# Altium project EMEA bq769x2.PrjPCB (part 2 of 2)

## Sheet MCU and Communication.SchDoc
size 431 x 279 mm; Date: Not shown in title block; ApprovedBy: Not shown in title block; CheckedBy: Not shown in title block; Author: Not shown in title block; CompanyName: Not shown in title block; Engineer: Not shown in title block; Organization: Not shown in title block; Address1: Not shown in title block; Address2: Not shown in title block; Address3: Not shown in title block; Address4: Not shown in title block; DocumentNumber: 1; Revision: Use project parameter SCH_Rev; SheetNumber: 4; SheetTotal: 7; PageSetup: Record=PageOptions¦CenterHorizontal=True¦CenterVertical=True¦PrintScale=1.00¦XCorrection=1.00¦YCorrection=1.00¦PrintKind=0¦BorderSize=5000000¦LeftOffset=0¦BottomOffset=0¦Orientation=2¦PaperLength=1000¦PaperWidth=1000¦Scale=100¦PaperSource=15¦PrintQuality=600¦MediaType=1¦DitherType=10¦PaperKind=Letter¦PrintScaleMode=1
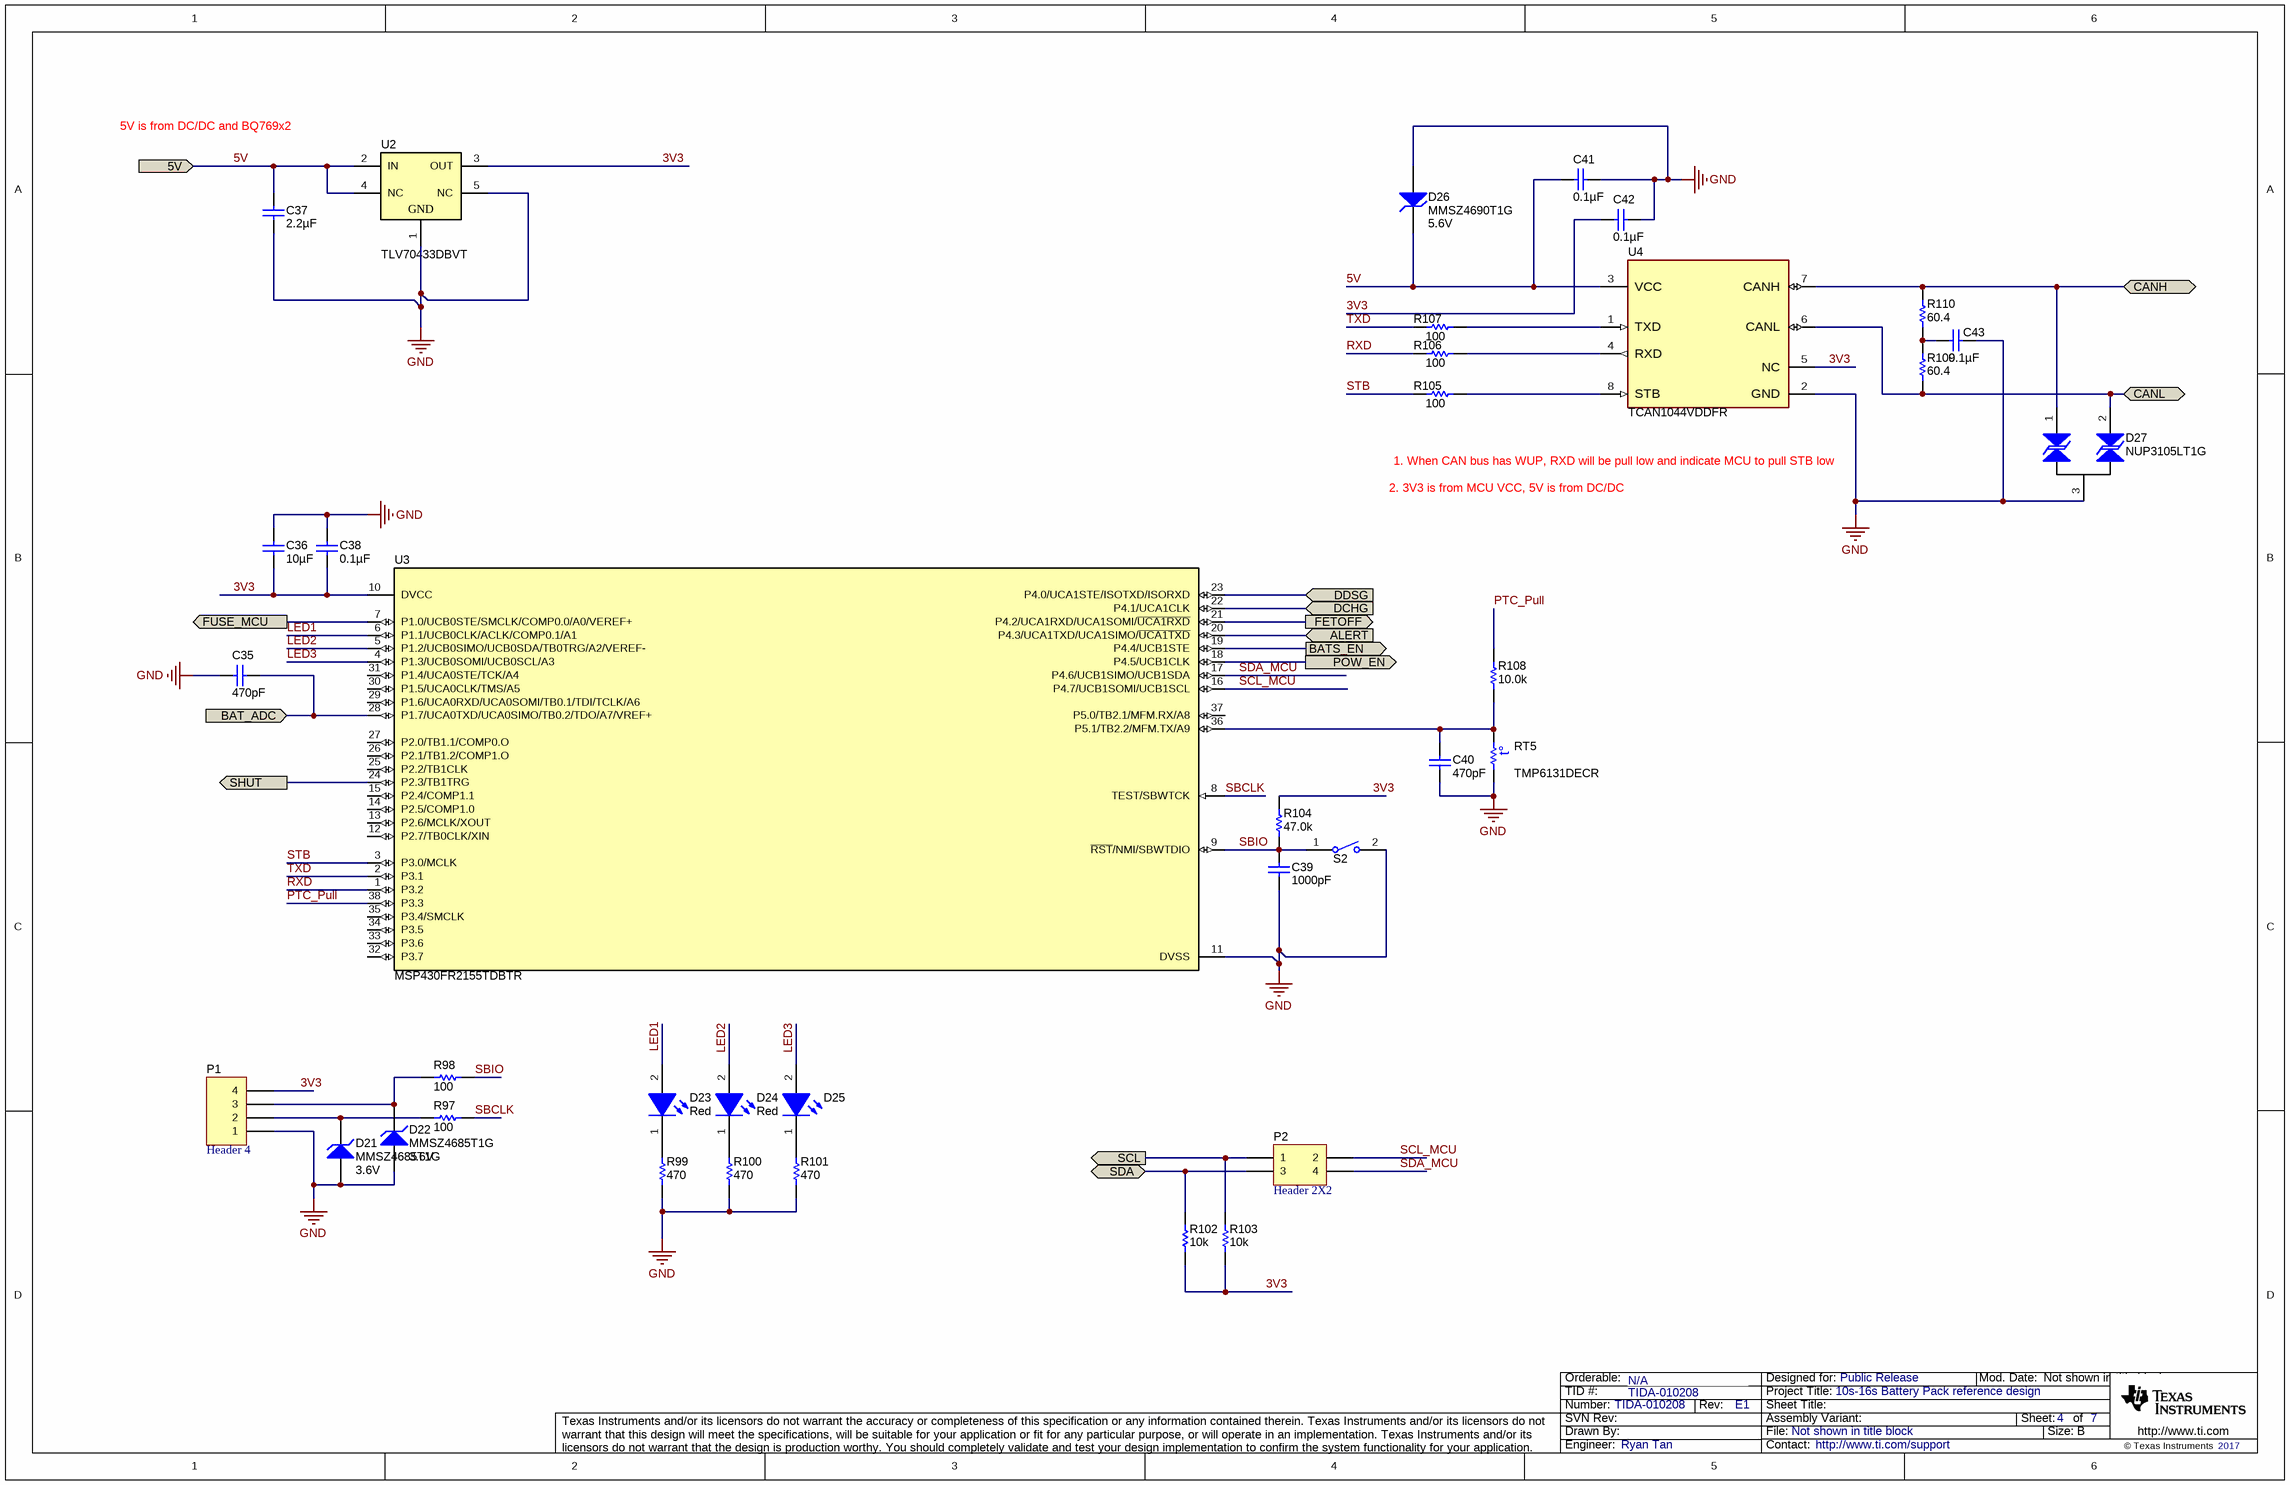
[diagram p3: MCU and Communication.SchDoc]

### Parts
C35  ValueDisplayed: 470pF  [0603]  (hidden comment: GRM188R71H471KA01D)
C36  ValueDisplayed: 10µF  [0805_HV]  (hidden comment: CL21B106KOQNNNE)
C37  ValueDisplayed: 2.2µF  [0603]  (hidden comment: EMK107BB7225MA-T)
C38  ValueDisplayed: 0.1µF  [0603]  (hidden comment: GRM188R71H104KA93D)
C39  ValueDisplayed: 1000pF  [0603]  (hidden comment: GRM1885C1H102JA01D)
C40  ValueDisplayed: 470pF  [0603]  (hidden comment: GRM188R71H471KA01D)
C41  ValueDisplayed: 0.1µF  [0603]  (hidden comment: GRM188R71H104KA93D)
C42  ValueDisplayed: 0.1µF  [0603]  (hidden comment: GRM188R71H104KA93D)
C43  ValueDisplayed: 0.1µF  [0603S]  (hidden comment: GRM188R71H104KA93D)
D21  MMSZ4685T1G  value 3.6V  [SOD-123]
D22  MMSZ4685T1G  value 3.6V  [SOD-123]
D23  value Red  [WL-SMCW_RED]  (hidden comment: 150060RS75000)
D24  value Red  [WL-SMCW_RED]  (hidden comment: 150060RS75000)
D25  150060RS75000  [WL-SMCW_RED]  (value not drawn)
D26  MMSZ4690T1G  value 5.6V  [SOD-123]
D27  NUP3105LT1G  [SOT-23]
P1  Header 4  [HDR1X4]
P2  Header 2X2  [HDR2X2]
R97  ValueDisplayed: 100  [0603]  (hidden comment: CRCW0603100RFKEA)
R98  ValueDisplayed: 100  [0603]  (hidden comment: CRCW0603100RFKEA)
R99  ValueDisplayed: 470  [0603]  (hidden comment: RC0603FR-07470RL)
R100  ValueDisplayed: 470  [0603]  (hidden comment: RC0603FR-07470RL)
R101  ValueDisplayed: 470  [0603]  (hidden comment: RC0603FR-07470RL)
R102  ValueDisplayed: 10k  [0603]  (hidden comment: CRCW060310K0JNEA)
R103  ValueDisplayed: 10k  [0603]  (hidden comment: CRCW060310K0JNEA)
R104  ValueDisplayed: 47.0k  [0603]  (hidden comment: RC0603FR-0747KL)
R105  ValueDisplayed: 100  [0603]  (hidden comment: CRCW0603100RFKEA)
R106  ValueDisplayed: 100  [0603]  (hidden comment: CRCW0603100RFKEA)
R107  ValueDisplayed: 100  [0603]  (hidden comment: CRCW0603100RFKEA)
R108  ValueDisplayed: 10.0k  [0603]  (hidden comment: CRCW060310K0FKEA)
R109  ValueDisplayed: 60.4  [0603S]  (hidden comment: RC0603FR-0760R4L)
R110  ValueDisplayed: 60.4  [0603S]  (hidden comment: RC0603FR-0760R4L)
RT5  TMP6131DECR  [DEC0002A]
S2  RS-032G05A3-SM RT  [SW_RS-032G05A3-SM]  (value not drawn)
U2  TLV70433DBVT  [DBV0005A_N]
U3  MSP430FR2155TDBTR  [DBT0038A_N]
U4  PartNumber: TCAN1044VDDFR  [DDF0008A-MFG]  (hidden comment: TCAN1044DDFRQ1)

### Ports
5V, ALERT (in), BAT_ADC (in), BATS_EN (out), CANH (bidir), CANL (bidir), DCHG (in), DDSG (in), FETOFF (out), FUSE_MCU (out), POW_EN (out), SCL (out), SDA (bidir), SHUT (out)

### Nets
GND: C35.1 C36.1 C37.2 C38.1 C39.2 C40.2 C41.2 C42.2 C43.1 D21.2(A) D22.2(A) D26.2(A) D27.3 P1.1 R99.1 R100.1 R101.1 RT5.1 S2.2 U2.1(GND) U2.5(NC) U3.11(DVSS) U4.2(GND)
3V3: C36.2 C38.2 C42.1 P1.4 R102.1 R103.1 R104.2 U2.3(OUT) U3.10(DVCC) U4.5(NC)
5V: C37.1 C41.1 D26.1(K) U2.2(IN) U2.4(NC) U4.3(VCC) ; port 5V
ALERT: U3.20(P4.3/UCA1TXD/UCA1SIMO/~{UCA1TXD}) ; port ALERT
BAT_ADC: C35.2 U3.28(P1.7/UCA0TXD/UCA0SIMO/TB0.2/TDO/A7/VREF+) ; port BAT_ADC
BATS_EN: U3.19(P4.4/UCB1STE) ; port BATS_EN
CANH: D27.1 R110.1 U4.7(CANH) ; port CANH
CANL: D27.2 R109.2 U4.6(CANL) ; port CANL
DCHG: U3.22(P4.1/UCA1CLK) ; port DCHG
DDSG: U3.23(P4.0/UCA1STE/ISOTXD/ISORXD) ; port DDSG
FETOFF: U3.21(P4.2/UCA1RXD/UCA1SOMI/~{UCA1RXD}) ; port FETOFF
FUSE_MCU: U3.7(P1.0/UCB0STE/SMCLK/COMP0.0/A0/VEREF+) ; port FUSE_MCU
LED1: D23.2(A) U3.6(P1.1/UCB0CLK/ACLK/COMP0.1/A1)
LED2: D24.2(A) U3.5(P1.2/UCB0SIMO/UCB0SDA/TB0TRG/A2/VEREF-)
LED3: D25.2(A) U3.4(P1.3/UCB0SOMI/UCB0SCL/A3)
POW_EN: U3.18(P4.5/UCB1CLK) ; port POW_EN
PTC_Pull: R108.2 U3.38(P3.3)
RXD: R106.2 U3.1(P3.2)
SBCLK: R97.1 U3.8(TEST/SBWTCK)
SBIO: C39.1 R98.1 R104.1 S2.1 U3.9(~{RST}/NMI/SBWTDIO)
SCL: P2.1 R103.2 ; port SCL
SCL_MCU: P2.2 U3.16(P4.7/UCB1SOMI/UCB1SCL)
SDA: P2.3 R102.2 ; port SDA
SDA_MCU: P2.4 U3.17(P4.6/UCB1SIMO/UCB1SDA)
SHUT: U3.24(P2.3/TB1TRG) ; port SHUT
STB: R105.2 U3.3(P3.0/MCLK)
TXD: R107.2 U3.2(P3.1)
NetC40_1: C40.1 R108.1 RT5.2 U3.36(P5.1/TB2.2/MFM.TX/A9)
NetC43_2: C43.2 R109.1 R110.2
NetD21_1: D21.1(K) P1.2 R97.2
NetD22_1: D22.1(K) P1.3 R98.2
NetD23_1: D23.1(K) R99.2
NetD24_1: D24.1(K) R100.2
NetD25_1: D25.1(K) R101.2
NetR105_1: R105.1 U4.8(STB)
NetR106_1: R106.1 U4.4(RXD)
NetR107_1: R107.1 U4.1(TXD)

Not connected (* = marked no-connect by the designer): U3 12(P2.7/TB0CLK/XIN) 13(P2.6/MCLK/XOUT) 14(P2.5/COMP1.0) 15(P2.4/COMP1.1) 25(P2.2/TB1CLK) 26(P2.1/TB1.2/COMP1.O) 27(P2.0/TB1.1/COMP0.O) 29(P1.6/UCA0RXD/UCA0SOMI/TB0.1/TDI/TCLK/A6) 30(P1.5/UCA0CLK/TMS/A5) 31(P1.4/UCA0STE/TCK/A4) 32(P3.7) 33(P3.6) 34(P3.5) 35(P3.4/SMCLK) 37(P5.0/TB2.1/MFM.RX/A8)

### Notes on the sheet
- 5V is from DC/DC and BQ769x2
- 2. 3V3 is from MCU VCC, 5V is from DC/DC
- 1. When CAN bus has WUP, RXD will be pull low and indicate MCU to pull STB low
- N/A

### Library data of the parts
C35 C40 = GRM188R71H471KA01D: CAP, CERM, 470 pF, 50 V,+/- 10%, X7R, 0603; Manufacturer: MuRata; Polarized: N; CompType: Capacitor; Value: 470pF; U/M: EA; Cap_F: 0.00000000047; Tolerance_%: 10; VDC_V: 50; Value2: 50V; TaMin_C: -55; TaMax_C: 125; SizeArea_mm2: 1.28; SizeAreaWB_mm2: 4.68; SizeX_mm: 1.6; SizeY_mm: 0.8; SizeZ_mm: 1; AEC Category: Q200; Green_Lifecycle: Active; Green_REACh: Passed
C36 = CL21B106KOQNNNE: CAP, CERM, 10 µF, 16 V,+/- 10%, X7R, 0805; Manufacturer: Samsung Electro-Mechanics; Polarized: N; CompType: Capacitor; Value: 10uF; U/M: EA; Cap_F: 0.00001; Tolerance_%: 10; VDC_V: 16; Value2: 16V; TaMin_C: -55; TaMax_C: 125; Cap_Case: 0805; SizeArea_mm2: 2.5; SizeAreaWB_mm2: 6.75; SizeX_mm: 2; SizeY_mm: 1.25; SizeZ_mm: 1.45; AEC Category: Q200; Green_Lifecycle: Active; Green_REACh: Passed
C37 = EMK107BB7225MA-T: CAP, CERM, 2.2 µF, 16 V,+/- 10%, X7R, 0603; Manufacturer: Taiyo Yuden; Polarized: N; CompType: Capacitor; Value: 2.2uF; U/M: EA; Cap_F: 0.0000022; Tolerance_%: 10; VDC_V: 16; Value2: 16V; TaMin_C: -55; TaMax_C: 125; SizeArea_mm2: 1.28; SizeAreaWB_mm2: 4.68; SizeX_mm: 1.6; SizeY_mm: 0.8; SizeZ_mm: 1; AEC Category: Q200
C38 C41 C42 = GRM188R71H104KA93D: CAP, CERM, 0.1 µF, 50 V,+/- 10%, X7R, 0603; Manufacturer: MuRata; Polarized: N; CompType: Capacitor; Value: 0.1uF; U/M: EA; Cap_F: 0.0000001; Tolerance_%: 10; VDC_V: 50; Value2: 50V; TaMin_C: -55; TaMax_C: 125; SizeArea_mm2: 1.28; SizeAreaWB_mm2: 4.68; SizeX_mm: 1.6; SizeY_mm: 0.8; SizeZ_mm: 1; AEC Category: Q200; Green_Lifecycle: Active; Green_REACh: Passed
C39 = GRM1885C1H102JA01D: CAP, CERM, 1000 pF, 50 V,+/- 5%, C0G/NP0, 0603; Manufacturer: MuRata; Polarized: N; CompType: Capacitor; Value: 1000pF; U/M: EA; Cap_F: 0.000000001; Tolerance_%: 5; VDC_V: 50; Value2: 50V; TaMin_C: -55; TaMax_C: 125; SizeArea_mm2: 1.28; SizeAreaWB_mm2: 4.68; SizeX_mm: 1.6; SizeY_mm: 0.8; SizeZ_mm: 1; AEC Category: Q200; Green_Lifecycle: Active; Green_REACh: Passed
C43 = GRM188R71H104KA93D: CAP, CERM, 0.1 µF, 50 V,+/- 10%, X7R, 0603; Manufacturer: MuRata; Polarized: N; CompType: Capacitor; Value: 0.1uF; U/M: EA; Cap_F: 0.0000001; Tolerance_%: 10; VDC_V: 50; Value2: 50V; TaMin_C: -55; TaMax_C: 125; Cap_Case: 0603; SizeArea_mm2: 1.28; SizeAreaWB_mm2: 4.68; SizeX_mm: 1.6; SizeY_mm: 0.8; SizeZ_mm: 1; AEC Category: Q200; Green_Lifecycle: Active; Green_REACh: Passed
D21 D22 = MMSZ4685T1G: Diode, Zener, 3.6 V, 500 mW, SOD-123; Manufacturer: ON Semiconductor; SymbolCreator: a0412235; U/M: EA; Power_W: 0.5; Vz_V: 3.6; Value1: 0.5W; RJA_CperW: 340; SizeAreaWB_mm2: 13.095; SizeArea_mm2: 6.545; SizeX_mm: 3.85; SizeY_mm: 1.7; SizeZ_mm: 1.35; AEC Category: Q101; Green_Lifecycle: Active; Green_REACh: Passed
D23-D25 = 150060RS75000: LED, Red, SMD; Manufacturer: Wurth Elektronik; Type: AlInGaP; Vf_V: 2; Value2: 2V; Io_A: 0.03; Vr_V: 5; Tjmax_C: 85; Power_TotalModule: 0.072; Value1: 0.072W; Angle: 140; U/M: EA; Green_Lifecycle: Active; Green_REACh: Passed
D26 = MMSZ4690T1G: Diode, Zener, 5.6 V, 500 mW, SOD-123; Manufacturer: ON Semiconductor; SymbolCreator: a0412235; U/M: EA; Power_W: 0.5; Vz_V: 5.6; Value1: 0.5W; RJA_CperW: 340; SizeAreaWB_mm2: 13.095; SizeArea_mm2: 6.545; SizeX_mm: 3.85; SizeY_mm: 1.7; SizeZ_mm: 1.35; AEC Category: Q101; Green_Lifecycle: Active; Green_REACh: Passed
D27 = NUP2105LT1G: Diode, TVS, Bi, 24 V, SOT-23; Manufacturer: ON Semiconductor; SymbolCreator: a0411947; Value: 24V; U/M: EA; Power_W: 0.35; Vr_V: 24; Value1: 0.35W; SizeAreaWB_mm2: 14; SizeArea_mm2: 7.5; SizeX_mm: 2.5; SizeY_mm: 3; SizeZ_mm: 1.1; AEC Category: Q101
P1 = Header 4: Header, 4-Pin
P2 = Header 2X2: Header, 2-Pin, Dual row
R97 R98 R105-R107 = CRCW0603100RFKEA: RES, 100, 1%, 0.1 W, 0603; Manufacturer: Vishay-Dale; CompType: Resistor; Value: 100; Value_Code: 100R; Tolerance_%: 1; Power_W: 0.1; Value2: 0.1W; VDC_V: 75; TempCo: 100 ppm/C; SizeArea_mm2: 1.28; SizeX_mm: 1.6; SizeY_mm: 0.8; EIA_Code: E96; U/M: EA; AEC Category: Q200; Green_Lifecycle: Active; Green_REACh: Passed
R99-R101 = RC0603FR-07470RL: RES, 470, 1%, 0.1 W, 0603; Manufacturer: Yageo America; CompType: Resistor; Value: 470; Value_Code: 470R; Tolerance_%: 1; Power_W: 0.1; Value2: 0.1W; VDC_V: 150; TempCo: 200 ppm/C; SizeArea_mm2: 1.28; SizeX_mm: 1.6; SizeY_mm: 0.8; U/M: EA; AEC Category: Q200; Green_Lifecycle: Active; Green_REACh: Passed
R102 R103 = CRCW060310K0JNEA: RES, 10 k, 5%, 0.1 W, 0603; Manufacturer: Vishay-Dale; CompType: Resistor; Value: 10k; Res_ohm: 10000; Value_Code: 10k0; Tolerance_%: 5; Power_W: 0.1; Value2: 0.1W; VDC_V: 75; TempCo: 200 ppm/C; SizeArea_mm2: 1.28; SizeX_mm: 1.6; SizeY_mm: 0.8; SizeZ_mm: 1; EIA_Code: E24; U/M: EA; AEC Category: Q200; Green_Lifecycle: Active; Green_REACh: Passed
R104 = RC0603FR-0747KL: RES, 47.0 k, 1%, 0.1 W, 0603; Manufacturer: Yageo America; CompType: Resistor; Value: 47.0k; Res_ohm: 47000; Value_Code: 47k0; Tolerance_%: 1; Power_W: 0.1; Value2: 0.1W; VDC_V: 150; TempCo: 200 ppm/C; SizeArea_mm2: 1.28; SizeX_mm: 1.6; SizeY_mm: 0.8; U/M: EA; AEC Category: Q200; Green_Lifecycle: Active; Green_REACh: Passed
R108 = CRCW060310K0FKEA: RES, 10.0 k, 1%, 0.1 W, 0603; Manufacturer: Vishay-Dale; CompType: Resistor; Value: 10.0k; Res_ohm: 10000; Value_Code: 10k0; Tolerance_%: 1; Power_W: 0.1; Value2: 0.1W; VDC_V: 75; TempCo: 100 ppm/C; SizeArea_mm2: 1.28; SizeX_mm: 1.6; SizeY_mm: 0.8; EIA_Code: E96; U/M: EA; AEC Category: Q200; Green_Lifecycle: Active; Green_REACh: Passed
R109 R110 = RC0603FR-0760R4L: RES, 60.4, 1%, 0.1 W, 0603; Manufacturer: Yageo America; CompType: Resistor; Value: 60.4; Value_Code: 60R4; Tolerance_%: 1; Power_W: 0.1; Value2: 0.1W; VDC_V: 150; TempCo: 200 ppm/C; SizeArea_mm2: 1.28; SizeX_mm: 1.6; SizeY_mm: 0.8; EIA_Code: E96; U/M: EA; AEC Category: Q200
RT5 = CMP-0084566-1: Thermistor, DEC0002A (X1SON-2); Alternate Manufacturer: Texas Instruments; Alternate PartNumber: TMP6131DECT; CompType: IC; AEC Category: Q200; SizeX_mm: 1; AEC Qualified: N; SizeZ_mm: 0.5; SizeArea_mm2: 0.6; SizeAreaWB_mm2: 3.2
S2 = RS-032G05A3-SM RT: Switch, Tactile, SPST-NO, 0.05A, 12V, SMD; Manufacturer: C&K Components; SymbolCreator: a0799628; VDC_V: 12; SwitchFunction: Off-Mom; PositionCount: 1; CurrentRating_mA: 50; Green_Lifecycle: Not Set; Green_REACh: Incomplete
U2 = TLV70433DBVT: Single Output LDO, 150 mA, Fixed 3.3 V Output, 2.5 to 24 V Input, with Ultra-Low IQ, 5-pin SOT-23 (DBV), -40 to 125 degC, Green (RoHS & no Sb/Br); Manufacturer: Texas Instruments; Alternate PartNumber: Equivalent; Accuracy(%): 2; Fixed Output Options(V): 3.3; Iout(Max)(A): 0.15; Iq(Typ)(mA): 0.003; SubFamily: Single Channel LDO; Vdo(Typ)(mV): 400; Vin(Max)(V): 24; Vin(Min)(V): 2.5
U3 = CMP-0084060-1: 24MHz 105C ULP Microcontroller With 32 KB FRAM, 4 KB SRAM, 44 IO, 12-bit ADC, DBT0038A (TSSOP-38); Manufacturer: Texas Instruments; Rating: Catalog; SizeAreaWB_mm2: 98.28; SizeArea_mm2: 62.08; AEC Qualified: N; AEC Category: Q200; SizeZ_mm: 1.2; SizeY_mm: 9.7; CompType: IC; SizeX_mm: 6.4
U4 = CMP-0089901-1: Automotive High Speed CAN Transceiver; Manufacturer: Texas Instruments; Min Supply Voltage: 4.5V; TaMin_C: -40°C; AEC Grade: Grade 1; Standoff Height: 0mm; SizeZ_mm: 1.1mm; TaMax_C: +125°C; Max Supply Voltage: 5.5V; Nominal Supply Current: 5-180mA; TJmax_C: +150°C; AEC Qualified: Yes

## Sheet High-side MOSFETs and driver.SchDoc
size 431 x 279 mm; Date: Not shown in title block; ApprovedBy: Not shown in title block; CheckedBy: Not shown in title block; Author: Not shown in title block; CompanyName: Not shown in title block; Engineer: Not shown in title block; Organization: Not shown in title block; Address1: Not shown in title block; Address2: Not shown in title block; Address3: Not shown in title block; Address4: Not shown in title block; DocumentNumber: 1; Revision: Use project parameter SCH_Rev; SheetNumber: 6; SheetTotal: 7; PageSetup: Record=PageOptions¦CenterHorizontal=True¦CenterVertical=True¦PrintScale=1.00¦XCorrection=1.00¦YCorrection=1.00¦PrintKind=0¦BorderSize=5000000¦LeftOffset=0¦BottomOffset=0¦Orientation=2¦PaperLength=1000¦PaperWidth=1000¦Scale=100¦PaperSource=15¦PrintQuality=600¦MediaType=1¦DitherType=10¦PaperKind=Letter¦PrintScaleMode=1
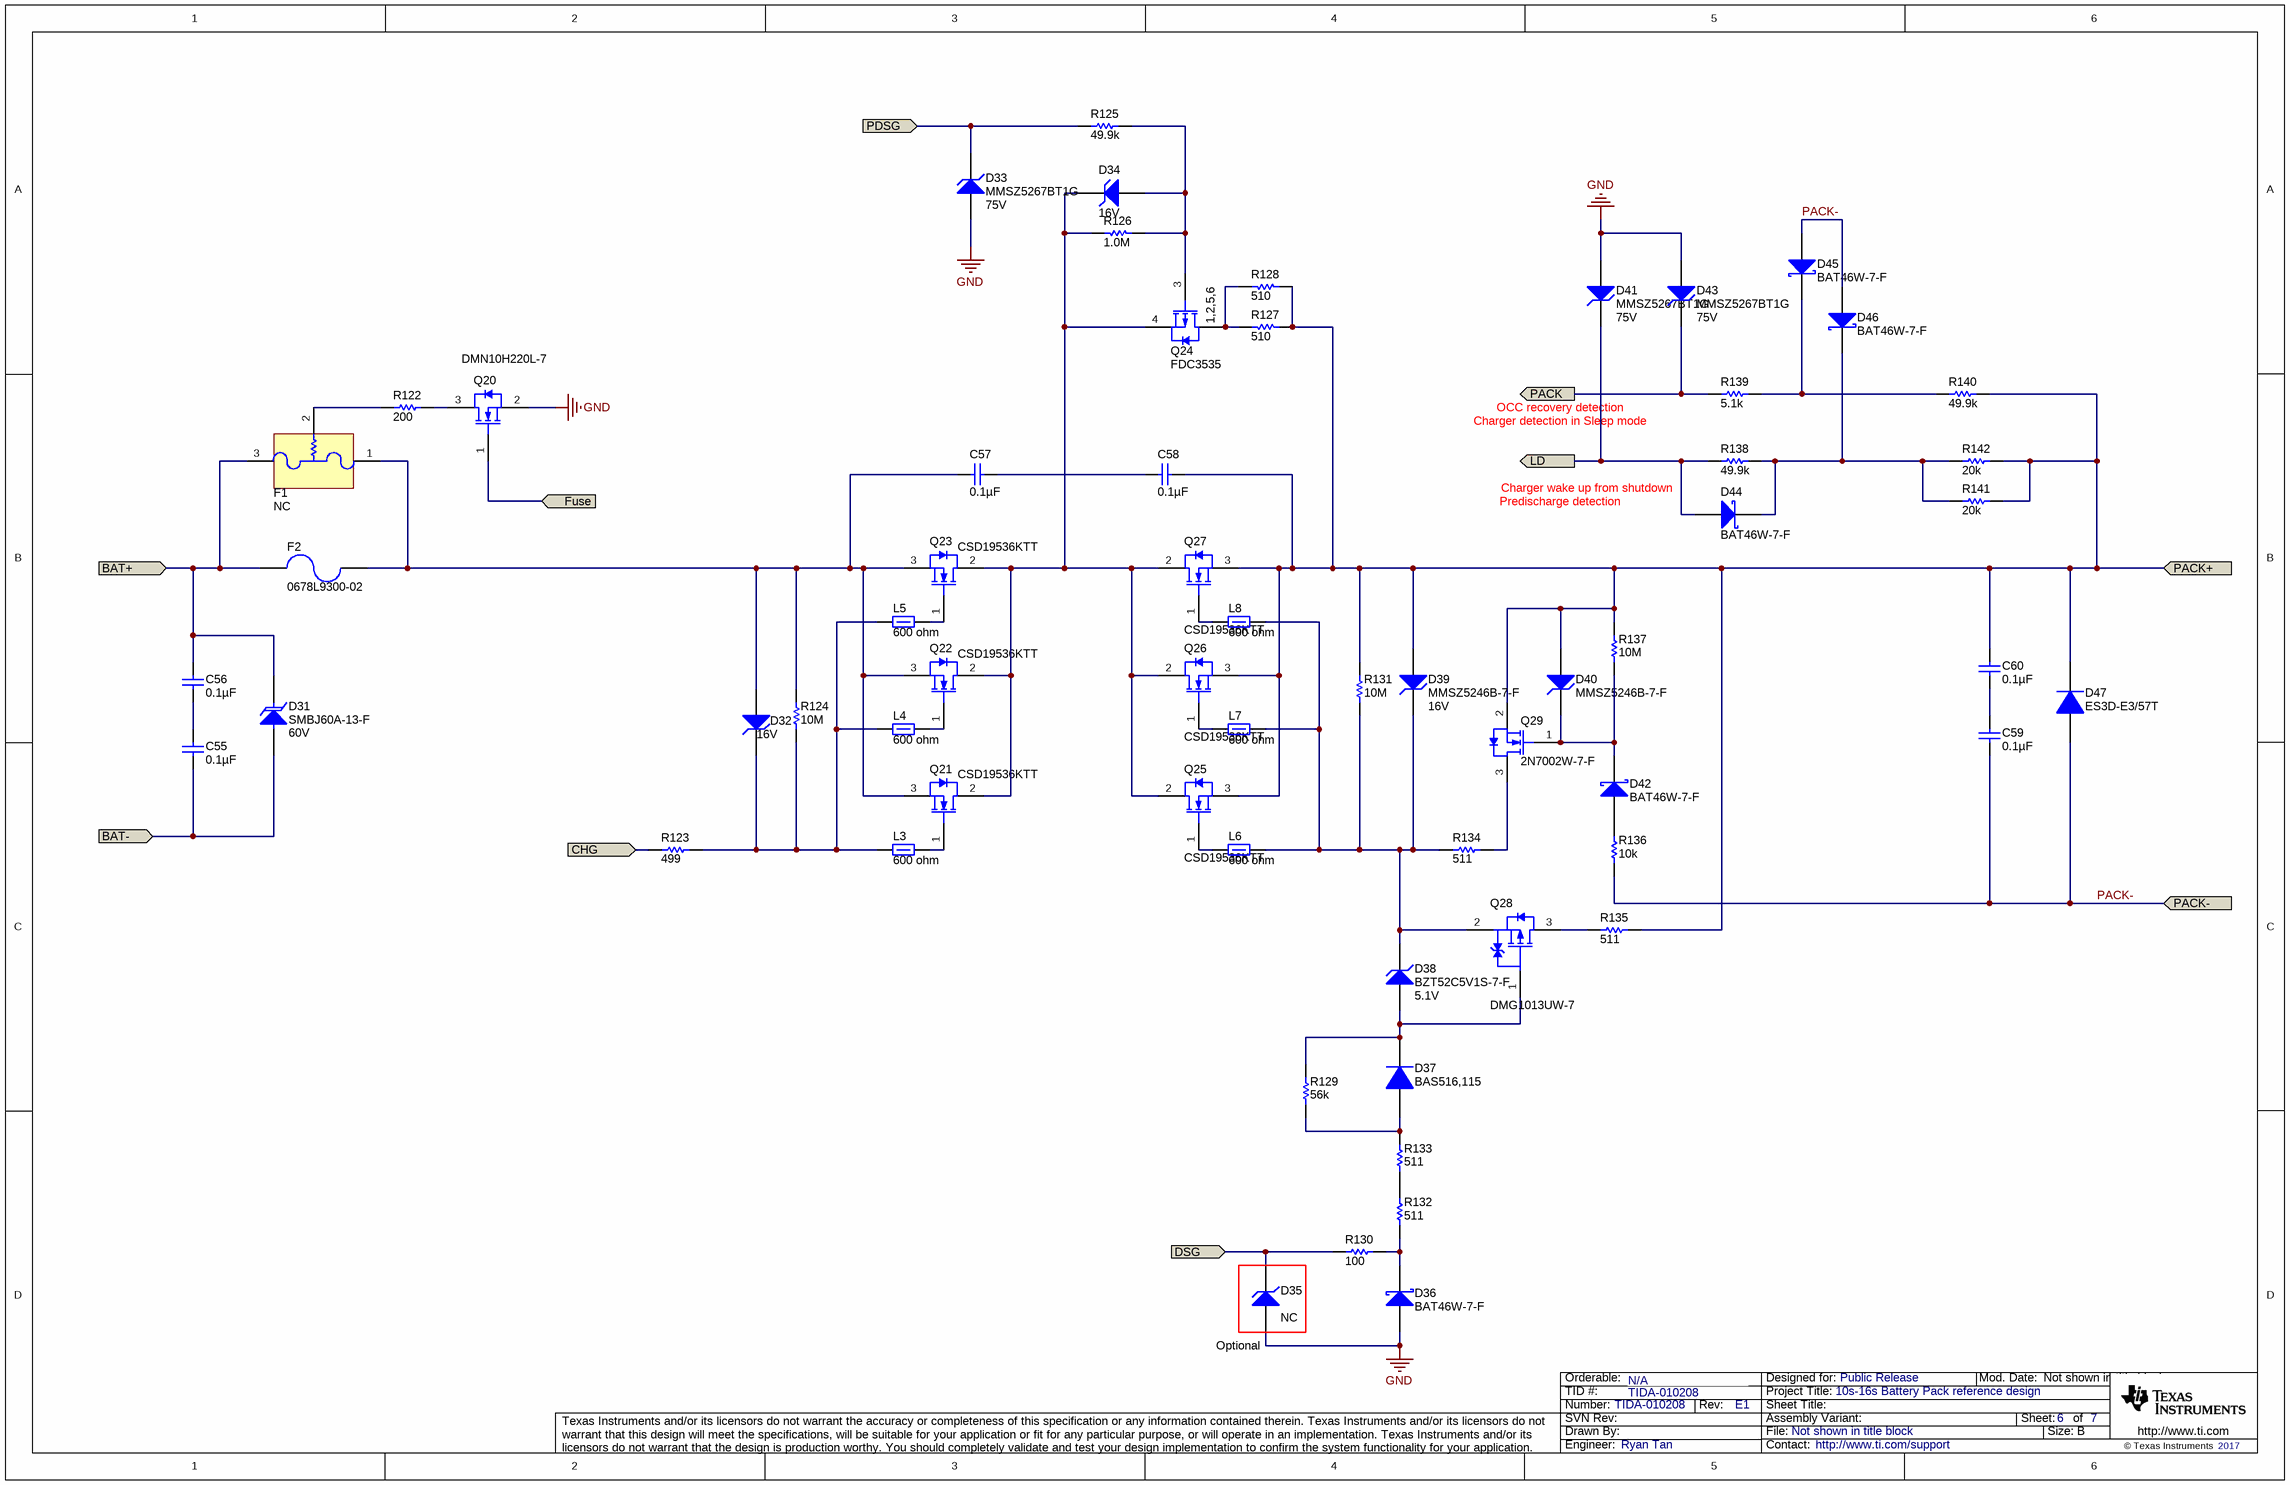
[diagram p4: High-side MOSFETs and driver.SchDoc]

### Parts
C55  ValueDisplayed: 0.1µF  [0603]  (hidden comment: GRM188R72A104KA35D)
C56  ValueDisplayed: 0.1µF  [0603]  (hidden comment: GRM188R72A104KA35D)
C57  ValueDisplayed: 0.1µF  [0603]  (hidden comment: GRM188R72A104KA35D)
C58  ValueDisplayed: 0.1µF  [0603]  (hidden comment: GRM188R72A104KA35D)
C59  ValueDisplayed: 0.1µF  [0603]  (hidden comment: GRM188R72A104KA35D)
C60  ValueDisplayed: 0.1µF  [0603]  (hidden comment: GRM188R72A104KA35D)
D31  SMBJ60A-13-F  value 60V  [SMB]
D32  value 16V  [SOD-123]  (hidden comment: MMSZ5246B-7-F)
D33  MMSZ5267BT1G  value 75V  [SOD-123]
D34  value 16V  [SOD-123]  (hidden comment: MMSZ5246B-7-F)
D35  value NC  [SOD-123]  (hidden comment: MMSZ5263BT1G)
D36  BAT46W-7-F  [SOD-123]
D37  BAS516,115  [SOD-523]
D38  BZT52C5V1S-7-F  value 5.1V  [SOD-323]
D39  MMSZ5246B-7-F  value 16V  [SOD-123]
D40  MMSZ5246B-7-F  [SOD-123]
D41  MMSZ5267BT1G  value 75V  [SOD-123]
D42  BAT46W-7-F  [SOD-123]
D43  MMSZ5267BT1G  value 75V  [SOD-123]
D44  BAT46W-7-F  [SOD-123]
D45  BAT46W-7-F  [SOD-123]
D46  BAT46W-7-F  [SOD-123]
D47  ES3D-E3/57T  [SMC]
F1  NC  [FUSE_SFK-xx30x]
F2  0678L9300-02  [Fuse_0678L]
L3  ValueDisplayed: 600 ohm  [0603]  (hidden comment: 74279265)
L4  ValueDisplayed: 600 ohm  [0603]  (hidden comment: 74279265)
L5  ValueDisplayed: 600 ohm  [0603]  (hidden comment: 74279265)
L6  ValueDisplayed: 600 ohm  [0603]  (hidden comment: 74279265)
L7  ValueDisplayed: 600 ohm  [0603]  (hidden comment: 74279265)
L8  ValueDisplayed: 600 ohm  [0603]  (hidden comment: 74279265)
Q20  DMN10H220L-7  [SOT-23]
Q21  CSD19536KTT  [KTT0002A_N]
Q22  CSD19536KTT  [KTT0002A_N]
Q23  CSD19536KTT  [KTT0002A_N]
Q24  FDC3535  [SSOT-6]
Q25  CSD19536KTT  [KTT0002A_N]
Q26  CSD19536KTT  [KTT0002A_N]
Q27  CSD19536KTT  [KTT0002A_N]
Q28  DMG1013UW-7  [SOT-323]
Q29  2N7002W-7-F  [SOT-323]
R122  ValueDisplayed: 200  [0603]  (hidden comment: CRCW0603200RFKEA)
R123  ValueDisplayed: 499  [1206L]  (hidden comment: ERJ-8ENF4990V)
R124  ValueDisplayed: 10M  [0603]  (hidden comment: CRCW060310M0JNEA)
R125  ValueDisplayed: 49.9k  [0603]  (hidden comment: RT0603BRD0749K9L)
R126  ValueDisplayed: 1.0M  [0603]  (hidden comment: CRCW06031M00JNEA)
R127  ValueDisplayed: 510  [2512]  (hidden comment: RC2512JK-07510RL)
R128  ValueDisplayed: 510  [2512]  (hidden comment: RC2512JK-07510RL)
R129  ValueDisplayed: 56k  [0805_HV]  (hidden comment: RC0805JR-0756KL)
R130  ValueDisplayed: 100  [0603]  (hidden comment: CRCW0603100RFKEA)
R131  ValueDisplayed: 10M  [0603]  (hidden comment: CRCW060310M0JNEA)
R132  ValueDisplayed: 511  [0805_HV1]  (hidden comment: CRCW0805511RFKEA)
R133  ValueDisplayed: 511  [0805_HV]  (hidden comment: CRCW0805511RFKEA)
R134  ValueDisplayed: 511  [0805_HV]  (hidden comment: CRCW0805511RFKEA)
R135  ValueDisplayed: 511  [0603]  (hidden comment: CRCW0603511RFKEA)
R136  ValueDisplayed: 10k  [0603]  (hidden comment: CRCW060310K0JNEA)
R137  ValueDisplayed: 10M  [0603]  (hidden comment: CRCW060310M0JNEA)
R138  ValueDisplayed: 49.9k  [0603]  (hidden comment: RT0603BRD0749K9L)
R139  ValueDisplayed: 5.1k  [0603]  (hidden comment: CRCW06035K10JNEA)
R140  ValueDisplayed: 49.9k  [0603]  (hidden comment: RT0603BRD0749K9L)
R141  ValueDisplayed: 20k  [0603]  (hidden comment: CRCW060320K0JNEA)
R142  ValueDisplayed: 20k  [0603]  (hidden comment: CRCW060320K0JNEA)

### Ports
BAT+ (in), BAT- (in), CHG (in), DSG (in), Fuse (in), LD (out), PACK (out), PACK+ (in), PACK- (in), PDSG (in)

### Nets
GND: D33.2(A) D35.2(A) D36.2(A) D41.2(A) D43.2(A) Q20.2(S)
BAT+: C56.1 D31.1(K) F1.3(Fuse) F2.2 ; port BAT+
BAT-: C55.2 D31.2(A) ; port BAT-
CHG: R123.1 ; port CHG
DSG: D35.1(K) R130.1 ; port DSG
Fuse: Q20.1(G) ; port Fuse
LD: D41.1(K) D44.2(A) R138.1 ; port LD
PACK: D43.1(K) R139.1 ; port PACK
PACK+: C58.1 C60.1 D39.2(A) D40.2(A) D47.1(K) Q25.3(S) Q26.3(S) Q27.3(S) Q29.2(S) R127.1 R128.1 R131.2 R135.2 R137.1 R140.2 R141.2 R142.2 ; port PACK+
PACK-: C59.2 D45.2(A) D46.2(A) D47.2(A) R136.1 ; port PACK-
PDSG: D33.1(K) R125.1 ; port PDSG
NetC55_1: C55.1 C56.2
NetC57_1: C57.1 C58.2
NetC57_2: C57.2 D32.2(A) F1.1(Fuse) F2.1 Q21.3(S) Q22.3(S) Q23.3(S) R124.2
NetC59_1: C59.1 C60.2
NetD32_1: D32.1(K) L3.1 L4.1 L5.1 R123.2 R124.1
NetD34_1: D34.1(K) Q21.2(D) Q22.2(D) Q23.2(D) Q24.4(S) Q25.2(D) Q26.2(D) Q27.2(D) R126.2
NetD34_2: D34.2(A) Q24.3(G) R125.2 R126.1
NetD36_1: D36.1(K) R130.2 R132.1
NetD37_1: D37.1(K) D38.2(A) Q28.1(G) R129.2
NetD37_2: D37.2(A) R129.1 R133.1
NetD38_1: D38.1(K) D39.1(K) L6.1 L7.1 L8.1 Q28.2(S) R131.1 R134.1
NetD40_1: D40.1(K) D42.1(K) Q29.1(G) R137.2
NetD42_2: D42.2(A) R136.2
NetD44_1: D44.1(K) D46.1(K) R138.2 R141.1 R142.1
NetD45_1: D45.1(K) R139.2 R140.1
NetF1_2: F1.2(Heater) R122.1
NetL3_2: L3.2 Q21.1(G)
NetL4_2: L4.2 Q22.1(G)
NetL5_2: L5.2 Q23.1(G)
NetL6_2: L6.2 Q25.1(G)
NetL7_2: L7.2 Q26.1(G)
NetL8_2: L8.2 Q27.1(G)
NetQ20_3: Q20.3(D) R122.2
NetQ24_1: Q24.1(D) Q24.2(D) Q24.5(D) Q24.6(D) R127.2 R128.2
NetQ28_3: Q28.3(D) R135.1
NetQ29_3: Q29.3(D) R134.2
NetR132_2: R132.2 R133.2

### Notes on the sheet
- OCC recovery detection
- Charger detection in Sleep mode
- Predischarge detection
- Charger wake up from shutdown
- (near D35) Optional
- N/A

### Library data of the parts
C55-C60 = GRM188R72A104KA35D: CAP, CERM, 0.1 µF, 100 V,+/- 10%, X7R, 0603; Manufacturer: MuRata; Polarized: N; CompType: Capacitor; Value: 0.1uF; U/M: EA; Cap_F: 0.0000001; Tolerance_%: 10; VDC_V: 100; Value2: 100V; TaMin_C: -55; TaMax_C: 125; SizeArea_mm2: 1.28; SizeAreaWB_mm2: 4.68; SizeX_mm: 1.6; SizeY_mm: 0.8; SizeZ_mm: 1; AEC Category: Q200; Green_Lifecycle: Active; Green_REACh: Passed
D31 = SMBJ60A-13-F: Diode, TVS, Uni, 60 V, 96.8 Vc, SMB; Manufacturer: Diodes Inc.; U/M: EA; Power_W: 5; Vr_V: 60; Value1: 5W; SizeAreaWB_mm2: 44.156; SizeArea_mm2: 21.336; SizeX_mm: 5.6; SizeY_mm: 3.81; SizeZ_mm: 2.6; AEC Category: Q101
D32 D34 D39 = MMSZ5246B-7-F: Diode, Zener, 16 V, 500 mW, SOD-123; Manufacturer: Diodes Inc.; SymbolCreator: a0412235; U/M: EA; Power_W: 0.5; Vz_V: 16; Value1: 0.5W; RJA_CperW: 350; SizeAreaWB_mm2: 13.095; SizeArea_mm2: 6.545; SizeX_mm: 3.85; SizeY_mm: 1.7; SizeZ_mm: 1.35; AEC Category: Q101; Green_Lifecycle: Active; Green_REACh: Passed
D33 D35 D41 D43 = MMSZ5263BT1G: Diode, Zener, 75V, 500 mW, AEC-Q101, SOD-123; Manufacturer: ON Semiconductor; SymbolCreator: a0412235; U/M: EA; Power_W: 0.5; Vz_V: 56; Value1: 0.5W; RJA_CperW: 340; SizeAreaWB_mm2: 13.095; SizeArea_mm2: 6.545; SizeX_mm: 3.85; SizeY_mm: 1.7; SizeZ_mm: 1.35; AEC Category: Q101; AEC Qualified: Y
D36 D42 D44-D46 = BAT46W-7-F: Diode, Schottky, 100 V, 0.15 A, SOD-123; Manufacturer: Diodes Inc.; U/M: EA; Vf_V: 0.6; Value: 100V; Value1: 0.15A; Value2: 0.6V; Io_A: 0.15; Vr_V: 100; SizeAreaWB_mm2: 13.095; SizeArea_mm2: 6.545; SizeX_mm: 3.85; SizeY_mm: 1.7; SizeZ_mm: 1.35; AEC Category: Q101; Green_Lifecycle: Active; Green_REACh: Passed
D37 = BAS516,115: Diode, Switching, 100 V, 0.25 A, SOD-523; Manufacturer: Nexperia; U/M: EA; Vf_V: 1.25; Value: 100V; Value1: 0.25A; Value2: 1.25V; Io_A: 0.25; Vr_V: 100; TJmax_C: 150; SizeAreaWB_mm2: 5.13; SizeArea_mm2: 1.53; SizeX_mm: 1.7; SizeY_mm: 0.9; SizeZ_mm: 0.65; AEC Category: Q101; Green_Lifecycle: Not Set; Green_REACh: Incomplete
D38 = BZT52C5V1S-7-F: Diode, Zener, 5.1 V, 200 mW, SOD-323; Manufacturer: Diodes Inc.; SymbolCreator: a0412235; U/M: EA; Power_W: 0.2; Vz_V: 5.1; Value1: 0.2W; RJA_CperW: 625; SizeAreaWB_mm2: 8.695; SizeArea_mm2: 3.645; SizeX_mm: 2.7; SizeY_mm: 1.35; SizeZ_mm: 1; AEC Category: Q101; Green_Lifecycle: Active; Green_REACh: Passed
D40 = MMSZ5246B-7-F: Diode, Zener, 16 V, 500 mW, SOD-123; Manufacturer: Diodes Inc.; SymbolCreator: a0412235; Value: 16V; U/M: EA; Power_W: 0.5; Vz_V: 16; Value1: 0.5W; RJA_CperW: 350; SizeAreaWB_mm2: 13.095; SizeArea_mm2: 6.545; SizeX_mm: 3.85; SizeY_mm: 1.7; SizeZ_mm: 1.35; AEC Category: Q101; Green_Lifecycle: Active; Green_REACh: Passed
D47 = ES3D-E3/57T: Diode, Ultrafast, 200 V, 3 A, SMC; Manufacturer: Vishay-Semiconductor; U/M: EA; Vf_V: 0.9; Value: 200V; Value1: 3A; Value2: 0.9V; Io_A: 3; Vr_V: 200; TJmax_C: 150; SizeAreaWB_mm2: 83.2686; SizeArea_mm2: 50.5686; SizeX_mm: 8.13; SizeY_mm: 6.22; SizeZ_mm: 2.6; AEC Category: Q101; Green_Lifecycle: Not Set; Green_REACh: Incomplete
F1 = SFK-5030: Manufacturer: POLYTRONICS; SymbolCreator: x0208325; CompType: Fuse; VDC_V: 62; Irating_A: 30; Rtyp_Ohm: 0.0015
F2 = 0678L9150-02: Fuse, 30 A, 250 VAC, 72 VDC, SMD; Manufacturer: Bel Fuse; SizeAreaWB_mm2: 59.59; SizeArea_mm2: 29.89; SizeX_mm: 9.8; SizeY_mm: 3.05; SizeZ_mm: 3.18; VDC_V: 72; VAC_V: 250; Irating_A: 15; Rtyp_Ohm: 0.0036; MeltingTyp: 110
L3-L8 = 74279265: Ferrite Bead, 600 ohm @ 100 MHz, 0.2 A, 0603; Manufacturer: Wurth Elektronik; Value: 600 ohm; Imax_A: 0.2; DCR_ohm: 0.45; Value1: 0.45 ohm; Value2: 0.2A; SizeAreaWB_mm2: 4.68; SizeArea_mm2: 1.28; SizeX_mm: 1.6; SizeY_mm: 0.8; SizeZ_mm: 1; ZTyp@100MHz_Ohm: 600; Ztyp@1GHz_Ohm: 223.805; Green_Lifecycle: Active; Green_REACh: Passed
Q20 = DMN10H220L-7: MOSFET, N-CH, 100 V, 1.4 A, SOT-23; Manufacturer: Diodes Inc.; Alternate Manufacturer: None; U/M: EA; ChType: N; Value: 100V; VdsMax_V: 100; Value1: 0.25 ohm; Rdson45_ohm: 0.25; Value2: 4.1 nC; QgTyp_nC: 4.1; Vgs_V: 16; IdsMax_A: 1.4; SizeAreaWB_mm2: 14; SizeArea_mm2: 7.5; SizeX_mm: 2.5; SizeY_mm: 3; SizeZ_mm: 1.1; AEC Category: Q101; Green_Lifecycle: Active; Green_REACh: Passed
Q21-Q23 Q25-Q27 = CSD19536KTT: MOSFET, N-CH, 100 V, 200 A, KTT0002A (TO-263-2); Manufacturer: Texas Instruments; Alternate Manufacturer: None; U/M: EA; ChType: N; Value: 100V; VdsMax_V: 100; Value1: ? ohm; Value2: 118 nC; QgTyp_nC: 118; Vgs_V: 20; IdsMax_A: 200; SizeAreaWB_mm2: 198.208; SizeArea_mm2: 145.288; SizeX_mm: 14.3; SizeY_mm: 10.16; SizeZ_mm: 4.7; AEC Category: Q101
Q24 = FDC3535: MOSFET, P-CH, -80 V, -2.1 A, SSOT-6; Manufacturer: Fairchild Semiconductor; Alternate Manufacturer: None; U/M: EA; ChType: P; Value: -80V; Value1: 0.233 ohm; Rdson45_ohm: 0.233; Value2: 14 nC; QgTyp_nC: 14; Vgs_V: -20; SizeAreaWB_mm2: 14.82; SizeArea_mm2: 8.12; SizeX_mm: 2.8; SizeY_mm: 2.9; SizeZ_mm: 1.1; AEC Category: Q101; AEC Qualified: N; Green_Lifecycle: Active; Green_REACh: Passed
Q28 = DMG1013UW-7: MOSFET, P-CH, -20 V, -0.82 A, SOT-323; Manufacturer: Diodes Inc.; Alternate Manufacturer: None; SymbolCreator: a0411947; U/M: EA; ChType: P; Value: -20V; Value1: 0.75 ohm; Rdson45_ohm: 0.75; Value2: 0.622 nC; QgTyp_nC: 0.622; Vgs_V: -6; SizeAreaWB_mm2: 10.24; SizeArea_mm2: 4.84; SizeX_mm: 2.2; SizeZ_mm: 1.1; AEC Category: Q101; Green_Lifecycle: Active; Green_REACh: Passed
Q29 = 2N7002W-7-F: MOSFET, N-CH, 60 V, 0.115 A, SOT-323; Manufacturer: Diodes Inc.; Alternate Manufacturer: None; U/M: EA; ChType: N; Value: 60V; VdsMax_V: 60; Value1: 7.5 ohm; Rdson45_ohm: 7.5; Value2: ? nC; Vgs_V: 20; IdsMax_A: 0.115; SizeAreaWB_mm2: 10.24; SizeArea_mm2: 4.84; SizeX_mm: 2.2; SizeZ_mm: 1.1; AEC Category: Q101; Green_Lifecycle: Active; Green_REACh: Passed
R122 = CRCW0603200RFKEA: RES, 200, 1%, 0.1 W, 0603; Manufacturer: Vishay-Dale; CompType: Resistor; Value: 200; Value_Code: 200R; Tolerance_%: 1; Power_W: 0.1; Value2: 0.1W; VDC_V: 75; TempCo: 100 ppm/C; SizeArea_mm2: 1.28; SizeX_mm: 1.6; SizeY_mm: 0.8; EIA_Code: E96; U/M: EA; AEC Category: Q200; Green_Lifecycle: Active; Green_REACh: Passed
R123 = ERJ-8ENF4990V: RES, 499, 1%, 0.25 W, 1206; Manufacturer: Panasonic; CompType: Resistor; Value: 499; Value_Code: 499R; Tolerance_%: 1; Power_W: 0.25; Value2: 0.25W; VDC_V: 200; TempCo: 100 ppm/C; SizeArea_mm2: 5.12; SizeX_mm: 3.2; SizeY_mm: 1.6; SizeZ_mm: 1.35; EIA_Code: E96; U/M: EA; AEC Category: Q200
R124 R131 R137 = CRCW060310M0JNEA: RES, 10 M, 5%, 0.1 W, 0603; Manufacturer: Vishay-Dale; CompType: Resistor; Value: 10Meg; Res_ohm: 10000000; Value_Code: 10M0; Tolerance_%: 5; Power_W: 0.1; Value2: 0.1W; VDC_V: 75; TempCo: 200 ppm/C; SizeArea_mm2: 1.28; SizeX_mm: 1.6; SizeY_mm: 0.8; SizeZ_mm: 1; EIA_Code: E24; U/M: EA; AEC Category: Q200; Green_Lifecycle: Active; Green_REACh: Passed
R125 R138 R140 = RT0603BRD0749K9L: RES, 49.9 k, 0.1%, 0.1 W, 0603; Manufacturer: Yageo America; CompType: Resistor; Value: 49.9k; Res_ohm: 49900; Value_Code: 49k9; Tolerance_%: 0.1; Value2: 0.1W; VDC_V: 75; TempCo: 25 ppm/C; SizeArea_mm2: 1.28; SizeX_mm: 1.6; SizeY_mm: 0.8; SizeZ_mm: 1; EIA_Code: E192; U/M: EA; AEC Category: Q200
R126 = CRCW06031M00JNEA: RES, 1.0 M, 5%, 0.1 W, 0603; Manufacturer: Vishay-Dale; CompType: Resistor; Value: 1.0Meg; Res_ohm: 1000000; Value_Code: 1M00; Tolerance_%: 5; Power_W: 0.1; Value2: 0.1W; VDC_V: 75; TempCo: 200 ppm/C; SizeArea_mm2: 1.28; SizeX_mm: 1.6; SizeY_mm: 0.8; SizeZ_mm: 1; EIA_Code: E24; U/M: EA; AEC Category: Q200; Green_Lifecycle: Active; Green_REACh: Passed
R127 R128 = CRCW2512604RFKEG: RES SMD 510 OHM 5% 1W 2512; Manufacturer: Yageo; CompType: Resistor; Value: 510; Value_Code: 510R; Tolerance_%: 1; VDC_V: 500; TempCo: 100 ppm/C; SizeArea_mm2: 20.16; SizeX_mm: 6.3; SizeY_mm: 3.2; SizeZ_mm: 0.71; EIA_Code: E96; U/M: EA; AEC Category: Q200; AEC Qualified: Y; AEC Grade: 0
R129 = CRCW080556K0JNEA: RES, 56 k, 5%, 0.125 W, 0805; Manufacturer: Yageo; CompType: Resistor; Value: 56k; Res_ohm: 56000; Value_Code: 56k0; Tolerance_%: 5; Power_W: 0.125; Value2: 0.125W; VDC_V: 150; TempCo: 200 ppm/C; SizeArea_mm2: 2.5; SizeX_mm: 2; SizeY_mm: 1.25; SizeZ_mm: 1.45; EIA_Code: E24; U/M: EA; AEC Category: Q200
R130 = CRCW0603100RFKEA: as R97 on sheet MCU and Communication
R132-R134 = CRCW0805511RFKEA: RES, 511, 1%, 0.125 W, 0805; Manufacturer: Vishay-Dale; CompType: Resistor; Value: 511; Value_Code: 511R; Tolerance_%: 1; Power_W: 0.125; Value2: 0.125W; VDC_V: 150; TempCo: 100 ppm/C; SizeArea_mm2: 2.5; SizeX_mm: 2; SizeY_mm: 1.25; SizeZ_mm: 1.45; EIA_Code: E96; U/M: EA; AEC Category: Q200
R135 = CRCW0603511RFKEA: RES, 511, 1%, 0.1 W, 0603; Manufacturer: Vishay-Dale; CompType: Resistor; Value: 511; Value_Code: 511R; Tolerance_%: 1; Power_W: 0.1; Value2: 0.1W; VDC_V: 75; TempCo: 100 ppm/C; SizeArea_mm2: 1.28; SizeX_mm: 1.6; SizeY_mm: 0.8; EIA_Code: E96; U/M: EA; AEC Category: Q200; Green_Lifecycle: Active; Green_REACh: Passed
R136 = CRCW060310K0JNEA: as R102 on sheet MCU and Communication
R139 = CRCW06035K10JNEA: RES, 5.1 k, 5%, 0.1 W, 0603; Manufacturer: Vishay-Dale; CompType: Resistor; Value: 5.1k; Res_ohm: 5100; Value_Code: 5k10; Tolerance_%: 5; Power_W: 0.1; Value2: 0.1W; VDC_V: 75; TempCo: 200 ppm/C; SizeArea_mm2: 1.28; SizeX_mm: 1.6; SizeY_mm: 0.8; SizeZ_mm: 1; EIA_Code: E24; U/M: EA; AEC Category: Q200; Green_Lifecycle: Active; Green_REACh: Passed
R141 R142 = CRCW060320K0JNEA: RES, 20 k, 5%, 0.1 W, 0603; Manufacturer: Vishay-Dale; CompType: Resistor; Value: 20k; Res_ohm: 20000; Value_Code: 20k0; Tolerance_%: 5; Power_W: 0.1; Value2: 0.1W; VDC_V: 75; TempCo: 200 ppm/C; SizeArea_mm2: 1.28; SizeX_mm: 1.6; SizeY_mm: 0.8; SizeZ_mm: 1; EIA_Code: E24; U/M: EA; AEC Category: Q200; Green_Lifecycle: Active; Green_REACh: Passed

## Sheet EVM_Hardware.SchDoc
size 431 x 279 mm; Date: Not shown in title block; ApprovedBy: Not shown in title block; CheckedBy: Not shown in title block; Author: Not shown in title block; CompanyName: Not shown in title block; Engineer: Not shown in title block; Organization: Not shown in title block; Address1: Not shown in title block; Address2: Not shown in title block; Address3: Not shown in title block; Address4: Not shown in title block; DocumentNumber: 1; Revision: Use project parameter SCH_Rev; SheetNumber: 7; SheetTotal: 7; PageSetup: Record=PageOptions¦CenterHorizontal=True¦CenterVertical=True¦PrintScale=1.00¦XCorrection=1.00¦YCorrection=1.00¦PrintKind=0¦BorderSize=5000000¦LeftOffset=0¦BottomOffset=0¦Orientation=2¦PaperLength=1000¦PaperWidth=1000¦Scale=100¦PaperSource=15¦PrintQuality=600¦MediaType=1¦DitherType=10¦PaperKind=Letter¦PrintScaleMode=1
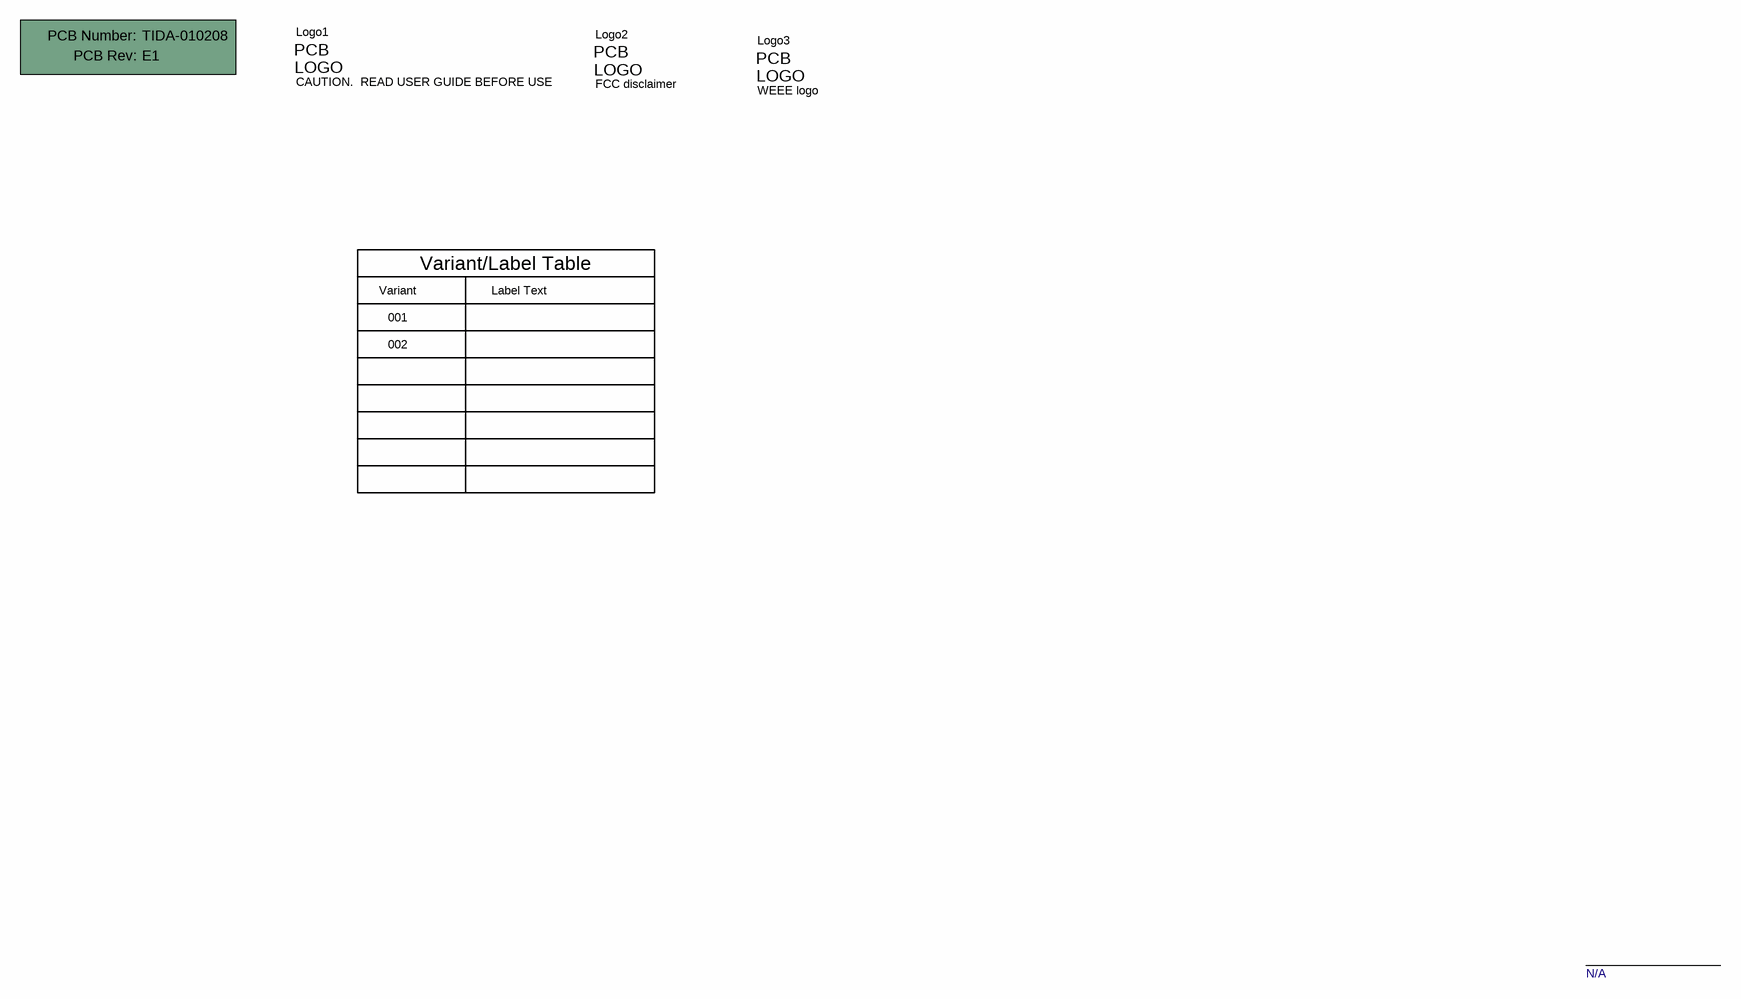
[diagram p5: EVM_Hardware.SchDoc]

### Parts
!PCB1  Printed Circuit Board  (value not drawn)  (mechanical)
Logo1  CAUTION.  READ USER GUIDE BEFORE USE  [IEC_Caution_Small]  (no BOM)
Logo2  FCC disclaimer  [FCC_disclaimer]  (no BOM)
Logo3  WEEE logo  [WEEE_Minimum]  (no BOM)

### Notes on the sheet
- Variant
- Variant/Label Table
- Label Text
- 001
- 002
- N/A

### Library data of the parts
!PCB1 = CMP-0003618-2: Manufacturer: Any; PartNumber: TIDA-010208
Logo1 = CMP-0074836-1: IEC 61010-1 Caution Warning; Library Reference: Logo; SymbolCreator: a0412235; Lib Reference: IEC_Caution
Logo2 = CMP-0074847-1: FCC_disclaimer; Library Reference: Logo
Logo3 = CMP-0074769-1

## Sheet CoverSheet.SchDoc
size 431 x 279 mm; Date: Not shown in title block; ApprovedBy: Not shown in title block; CheckedBy: Not shown in title block; Author: Not shown in title block; CompanyName: Not shown in title block; Engineer: Not shown in title block; Organization: Not shown in title block; Address1: Not shown in title block; Address2: Not shown in title block; Address3: Not shown in title block; Address4: Not shown in title block; DocumentNumber: 1; Revision: Use project parameter SCH_Rev; SheetNumber: 1; SheetTotal: 7; PageSetup: Record=PageOptions¦CenterHorizontal=True¦CenterVertical=True¦PrintScale=1.00¦XCorrection=1.00¦YCorrection=1.00¦PrintKind=0¦BorderSize=5000000¦LeftOffset=0¦BottomOffset=0¦Orientation=2¦PaperLength=1000¦PaperWidth=1000¦Scale=100¦PaperSource=15¦PrintQuality=600¦MediaType=1¦DitherType=10¦PaperKind=Letter¦PrintScaleMode=1
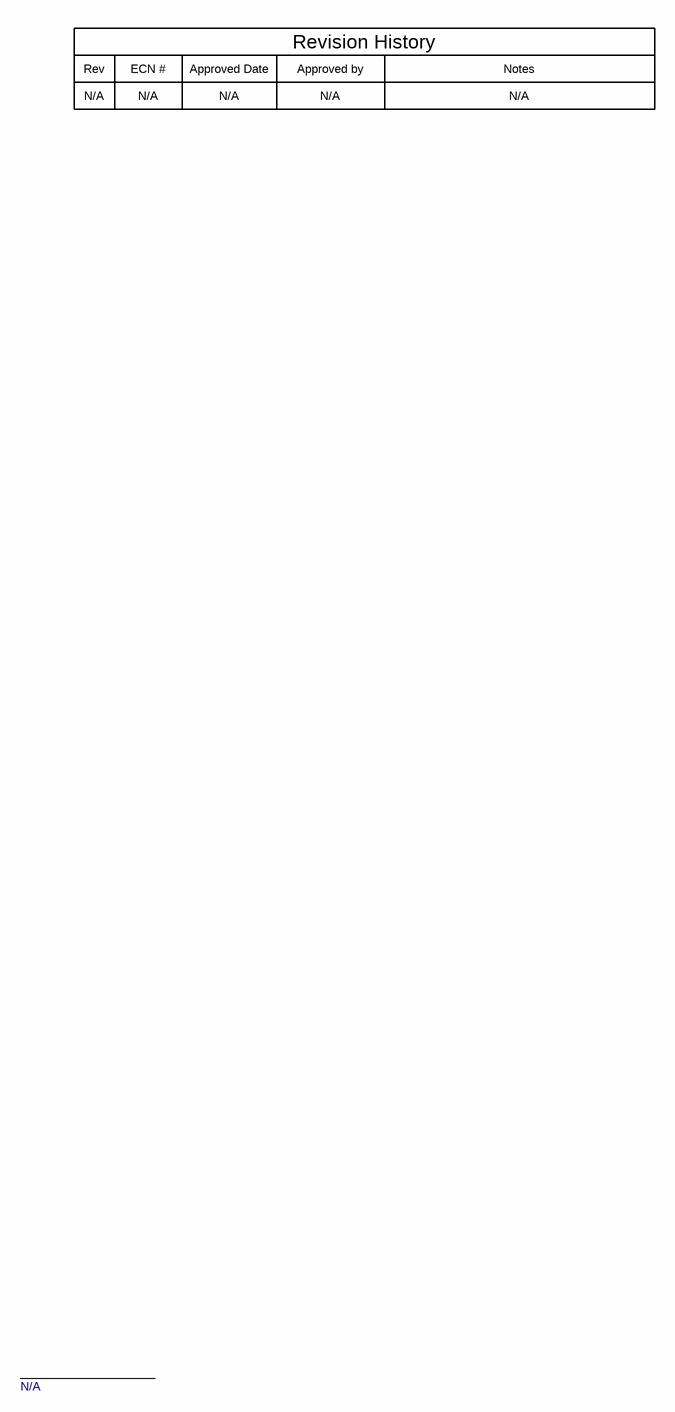
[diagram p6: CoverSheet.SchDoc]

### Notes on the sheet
- Rev
- N/A
- ECN #
- Approved Date
- Approved by
- Revision History
- Notes

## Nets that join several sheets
GND: High level sch (R111.1), Monitor and Cell balancing (28 pins), Aux power (12 pins), MCU and Communication (23 pins), High-side MOSFETs and driver (6 pins)
5V: High level sch (D28.1), Aux power (6 pins), MCU and Communication (6 pins)
5V_AFE: High level sch (D28.2), Monitor and Cell balancing (C25.1 U1.34)
ALERT: Monitor and Cell balancing (U1.25), MCU and Communication (U3.20)
BAT-: High level sch (R111.2 R112.1 R113.1), Monitor and Cell balancing (R96.1), High-side MOSFETs and driver (C55.2 D31.2)
BAT_ADC: Monitor and Cell balancing (R85.2 R86.1), MCU and Communication (C35.2 U3.28)
BATS_EN: Monitor and Cell balancing (Q18.1), MCU and Communication (U3.19)
CANH: High level sch (P4.1), MCU and Communication (D27.1 R110.1 U4.7)
CANL: High level sch (P4.2), MCU and Communication (D27.2 R109.2 U4.6)
Cell0: High level sch (P3.1), Monitor and Cell balancing (D1.2 Q1.2 R17.1)
Cell1: High level sch (P3.2), Monitor and Cell balancing (5 pins)
Cell2: High level sch (P3.3), Monitor and Cell balancing (5 pins)
Cell3: High level sch (P3.4), Monitor and Cell balancing (5 pins)
Cell4: High level sch (P3.5), Monitor and Cell balancing (5 pins)
Cell5: High level sch (P3.6), Monitor and Cell balancing (5 pins)
Cell6: High level sch (P3.7), Monitor and Cell balancing (5 pins)
Cell7: High level sch (P3.8), Monitor and Cell balancing (5 pins)
Cell8: High level sch (P3.9), Monitor and Cell balancing (5 pins)
Cell9: High level sch (P3.10), Monitor and Cell balancing (5 pins)
Cell10: High level sch (P3.11), Monitor and Cell balancing (6 pins)
Cell11: High level sch (P3.12), Monitor and Cell balancing (5 pins)
Cell12: High level sch (P3.13), Monitor and Cell balancing (6 pins)
Cell13: High level sch (P3.14), Monitor and Cell balancing (6 pins)
Cell14: High level sch (P3.15), Monitor and Cell balancing (6 pins)
Cell15: High level sch (P3.16), Monitor and Cell balancing (6 pins)
Cell16: High level sch (P3.17), Monitor and Cell balancing (8 pins), Aux power (D30.2)
CHG: Monitor and Cell balancing (U1.45), High-side MOSFETs and driver (R123.1)
DCHG: Monitor and Cell balancing (U1.31), MCU and Communication (U3.22)
DDSG: Monitor and Cell balancing (U1.32), MCU and Communication (U3.23)
DSG: Monitor and Cell balancing (U1.43), High-side MOSFETs and driver (D35.1 R130.1)
FETOFF: Monitor and Cell balancing (C23.1 R89.2 U1.30), MCU and Communication (U3.21)
Fuse: High level sch (D29.1 R114.2), High-side MOSFETs and driver (Q20.1)
FUSE_AFE: High level sch (R114.1), Monitor and Cell balancing (U1.38)
FUSE_MCU: High level sch (D29.2), MCU and Communication (U3.7)
LD: Monitor and Cell balancing (U1.41), High-side MOSFETs and driver (D41.1 D44.2 R138.1)
PACK: Monitor and Cell balancing (U1.42), High-side MOSFETs and driver (D43.1 R139.1)
PACK-: High level sch (R112.2 R113.2), Monitor and Cell balancing (R95.1), High-side MOSFETs and driver (5 pins)
PDSG: Monitor and Cell balancing (U1.39), High-side MOSFETs and driver (D33.1 R125.1)
POW_EN: Aux power (U5.3), MCU and Communication (U3.18)
SCL: Monitor and Cell balancing (R87.1), MCU and Communication (P2.1 R103.2)
SDA: Monitor and Cell balancing (R88.1), MCU and Communication (P2.3 R102.2)
SHUT: Monitor and Cell balancing (C24.1 R90.2 U1.33), MCU and Communication (U3.24)

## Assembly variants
16S-BQ76952: not fitted C44 C45 F1 R34 R35 R46 R47 R48 R49 R50 R64 R66 R67 R71
10S-BQ76942: not fitted C12 C13 C14 C20 C21 C22 C44 C45 D14 D15 D16 D17 D18 D19 F2 Q11 Q12 Q13 Q14 Q15 Q16 R34 R35 R40 R41 R42 R43 R44 R45 R46 R55 R56 R57 R58 R59 R60 R62 R63 R65 R68 R69 R70 R71 R72 R73 R74 R75 R76 R77 R78 R79 R80 R81 R82 R83
14S-BQ769142: not fitted C14 C21 C44 C45 D16 D18 F1 Q13 Q15 R44 R45 R47 R48 R49 R50 R59 R60 R64 R66 R67 R74 R75 R80 R81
